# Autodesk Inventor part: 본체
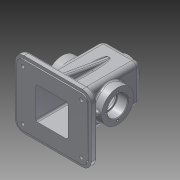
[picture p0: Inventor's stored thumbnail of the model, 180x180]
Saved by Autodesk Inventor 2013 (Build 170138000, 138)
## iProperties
Created: 2016-01
Part Number: 본체
Material: 알루미늄 6061
Document SubType Name: Modeling
Designer: User
Density: 2.71 g/cm^3
Mass: 889.915 g
Surface Area: 961.713 cm^2
Volume: 328.382 cm^3
Author: User
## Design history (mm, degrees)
sketch "스케치1"
  geometry: L1 (-32.5, 55)-(32.5, 55); L2 (32.5, 55)-(32.5, -55); L3 (32.5, -55)-(-32.5, -55); L4 (-32.5, -55)-(-32.5, 55); 1 further point
  constraints: 8 end point, 2 parallel, 1 horizontal, 1 perpendicular
  dimensions: "d0" = 65 distance of L1.start L1.end; "d2" = 110 distance of L3.end L1.start; "d3" = 32.5 distance from line of point (0, 0) L4; "d4" = 55 distance from line of point (0, 0) L1
extrude "돌출1" new body sketch "스케치1" stored distance "d5" = 65; taper "d6" = 0 deg
sketch "스케치2"
  geometry: L1 (65, 0)-(65, -65) reference; L2 (0, 0)-(65, 0) reference; L3 (0, 0)-(0, -65) reference; L4 (65, -65)-(0, -65) reference; L5 (5, -5)-(60, -5); L6 (60, -5)-(60, -60); L7 (60, -60)-(5, -60); L8 (5, -60)-(5, -5); 1 further point
  constraints: 8 end point, 2 parallel, 1 horizontal, 1 perpendicular
  dimensions: "d7" = 5 distance between parallel lines of L8 L3; "d8" = 5 distance between parallel lines of L2 L5; "d9" = 5 distance between parallel lines of L1 L6; "d10" = 5 distance between parallel lines of L4 L7
extrude "돌출2" cut sketch "스케치2" distance "d11" = 105; taper "d12" = 0 deg
node "작업 평면1"
sketch "스케치3"
  geometry: C1 r 20 at (32.5, 32.5); 1 further point
  constraints: 1 centre point, 1 coincident
  dimensions: "d14" = 40 diameter of C1
extrude "돌출3" join sketch "스케치3" stored distance "d15" = 105; taper "d16" = 0 deg
hole "구멍1" diameter "d19" = 21; stored, may be unused: countersink angle "d23" = 90 deg, drill point angle "d25" = 118 deg; dims "d17" = 10, "d18" = 10, "d20" = 6, "d21" = 4, "d22" = 2, "d24" = 8
node "작업 평면2"
sketch "스케치5"
  geometry: C1 r 27.5 at (32.5, 55); 1 further point
  constraints: 1 centre point, 1 coincident
  dimensions: "d28" = 55 diameter of C1
extrude "돌출4" join sketch "스케치5" stored distance "d29" = 105; taper "d30" = 0 deg
hole "구멍2" diameter "d33" = 35; stored, may be unused: countersink angle "d37" = 90 deg, drill point angle "d39" = 0 deg; dims "d31" = 10, "d32" = 10, "d34" = 6, "d35" = 4, "d36" = 2, "d38" = 17
hole "구멍3" diameter "d42" = 30; stored, may be unused: countersink angle "d46" = 90 deg, drill point angle "d48" = 0 deg; dims "d40" = 10, "d41" = 10, "d43" = 6, "d44" = 4, "d45" = 2, "d47" = 17
node "작업 평면3"
sketch "스케치6"
  geometry: L1 (-65, 57.5)-(65, 57.5); L2 (65, 57.5)-(65, -57.5); L3 (65, -57.5)-(-65, -57.5); L4 (-65, -57.5)-(-65, 57.5); 1 further point
  constraints: 8 end point, 2 parallel, 1 horizontal, 1 perpendicular
  dimensions: "d50" = 130 distance of L1.start L1.end; "d52" = 115 distance of L1.end L2.end; "d53" = 65 distance from line of point (0, 0) L4; "d54" = 57.5 distance from line of point (0, 0) L1
extrude "돌출5" join sketch "스케치6" distance "d55" = 10; taper "d56" = 0 deg
node "작업 평면4"
sketch "스케치8"
  geometry: L1 (-60, 52.5)-(60, 52.5); L2 (60, 52.5)-(60, -52.5); L3 (60, -52.5)-(-60, -52.5); L4 (-60, -52.5)-(-60, 52.5); L5 (65, -57.5)-(65, 57.5) reference; L6 (65, 57.5)-(-65, 57.5) reference; L7 (-27.5, 27.5)-(27.5, 27.5); L8 (27.5, 27.5)-(27.5, -27.5); L9 (27.5, -27.5)-(-27.5, -27.5); L10 (-27.5, -27.5)-(-27.5, 27.5); 1 further point
  constraints: 16 end point, 4 parallel, 2 horizontal, 2 perpendicular
  dimensions: "d61" = 120 distance of L1.start L1.end; "d63" = 105 distance of L1.end L2.end; "d64" = 5 distance between parallel lines of L5 L2; "d65" = 5 distance between parallel lines of L6 L1; "d66" = 55 distance of L7.start L7.end; "d67" = 55 distance of L7.end L8.end; "d68" = 27.5 distance from line of point (0, 0) L7; "d70" = 27.5 distance from line of point (0, 0) L10
extrude "돌출6" join sketch "스케치8" stored distance "d71" = 10; taper "d72" = 0 deg
extrude "돌출7" cut sketch "스케치8" distance "d73" = 89.75; taper "d74" = 0 deg
sketch "스케치9"
  geometry: L1 (-53, 57.5)-(-63, 57.5) reference; L2 (-53, 57.5)-(-53, -57.5) reference; L3 (55, 32.5)-(-53, 32.5) reference; L4 (-53, 47.5)-(32.069, 32.5); 1 further point
  constraints: 2 end point, 2 point on line
  dimensions: "d79" = 10 distance from line of L1 L4.start; "d80" = 10 deg angle of L1 L4
feature "리브1" sketch "스케치9" dims "d81" = 1, "d82" = 10, "d83" = 0, "d84" = 0, "d85" = 1, "d86" = 1
sketch "스케치11"
  geometry: L1 (-27.5, -65)-(-27.5, 50) reference; L2 (-65, -53)-(65, -53) reference; L3 (-42.5, -53)-(-42.5, -22.279); 1 further point
  constraints: 2 end point, 1 perpendicular, 1 point on line
  dimensions: "d87" = 15 distance from line of L1 L3.start
feature "리브2" sketch "스케치11" dims "d88" = 1, "d89" = 6, "d90" = 0, "d91" = 0, "d92" = 1, "d93" = 1
sketch "스케치12"
  geometry: L1 (-65, 57.5)-(65, 57.5) reference; C1 r 7.5 at (-50, 42.5); C2 r 7.5 at (50, 42.5); C3 r 7.5 at (50, -42.5); C4 r 7.5 at (-50, -42.5); 1 further point
  constraints: 4 centre point, 1 horizontal alignment
  dimensions: "d94" = 15 diameter of C1; "d95" = 15 diameter of C2; "d96" = 15 diameter of C3; "d97" = 15 diameter of C4; "d99" = 15 distance from line of C1.centre L1; "d100" = 100 distance of C2.centre C1.centre; "d102" = 85 distance of C4.centre C1.centre; "d103" = 100 distance of C3.centre C4.centre; "d105" = 42.5 vertical distance of point (0, 0) C2.centre; "d106" = 50 horizontal distance of C3.centre point (0, 0); "d187" = 50 horizontal distance of point (0, 0) C1.centre
extrude "돌출8" join sketch "스케치12" distance "d107" = 3; taper "d108" = 0 deg
hole "구멍4" diameter "d111" = 6; stored, may be unused: countersink angle "d115" = 90 deg, drill point angle "d117" = 0 deg; dims "d109" = 10, "d110" = 10, "d112" = 6, "d113" = 4, "d114" = 2, "d116" = 17
hole "구멍5" diameter "d120" = 6; stored, may be unused: countersink angle "d124" = 90 deg, drill point angle "d126" = 0 deg; dims "d118" = 10, "d119" = 10, "d121" = 6, "d122" = 4, "d123" = 2, "d125" = 17
hole "구멍6" diameter "d129" = 6; stored, may be unused: countersink angle "d133" = 90 deg, drill point angle "d135" = 0 deg; dims "d127" = 10, "d128" = 10, "d130" = 6, "d131" = 4, "d132" = 2, "d134" = 17
hole "구멍7" diameter "d138" = 6; stored, may be unused: countersink angle "d142" = 90 deg, drill point angle "d144" = 0 deg; dims "d136" = 10, "d137" = 10, "d139" = 6, "d140" = 4, "d141" = 2, "d143" = 17
node "작업 평면7"
feature "면 기울기1" dims angle "d145" = 5 deg
sketch "스케치13"
  geometry: L1 (-78.073, 0)-(132.155, 0); C1 r 10.5 at (0, 0) reference; C2 r 20 at (0, 0) reference; C3 r 1.5 at (0, 14.5); C4 r 1.5 at (-14.5, 0); C5 r 1.5 at (0, -14.5); C6 r 1.5 at (14.5, 0)
  constraints: 4 centre point, 2 end point, 1 horizontal, 1 point on line, 1 vertical alignment, 9 other
  dimensions: "d146" = 3 diameter of C3; "d147" = 29 diameter of C3.centre L1; "d150" = 360 deg dimension on C2.centre C3.centre (derived)
hole "구멍8" sketch "스케치13" at (-14.5, 0), (0, 14.5), (14.5, 0), (0, -14.5) diameter "d152" = 2.459; stored, may be unused: countersink angle "d156" = 90 deg, drill point angle "d158" = 0 deg; dims "d153" = 7, "d154" = 4, "d155" = 2, "d157" = 9
sketch "스케치14"
  geometry: L1 (-64.422, 0)-(123.164, 0); C1 r 27.5 at (0, 0) reference; C2 r 2 at (0, 21); C3 r 2 at (-21, 0); C4 r 2 at (0, -21); C5 r 2 at (21, 0)
  constraints: 4 centre point, 2 end point, 1 horizontal, 1 point on line, 1 vertical alignment, 9 other
  dimensions: "d159" = 4 diameter of C2; "d160" = 42 diameter of C2.centre L1; "d163" = 360 deg dimension on C1.centre C2.centre (derived)
hole "구멍9" sketch "스케치14" at (0, 21), (21, 0), (0, -21), (-21, 0) diameter "d165" = 3.242; stored, may be unused: countersink angle "d169" = 90 deg, drill point angle "d171" = 0 deg; dims "d166" = 8, "d167" = 4, "d168" = 2, "d170" = 10
fillet "모깎기1" dims "d172" = 15
fillet "모깎기2" dims "d173" = 3
fillet "모깎기3" dims "d174" = 8
fillet "모깎기5" dims "d176" = 8
fillet "모깎기6" dims "d177" = 3
fillet "모깎기7" dims "d178" = 3
chamfer "모따기1" distance "d179" = 1; stored, may be unused: second distance "d180" = 2, angle "d181" = 45 deg
fillet "모깎기8" dims "d185" = 3
sketch "스케치15"
  geometry: L1 (4.5, 18)-(44.5, 18) reference; L2 (-8, 0)-(-8, -97) reference; 1 further point
  constraints: 1 other
  dimensions: "d188" = 26 distance from line of point (24.5, -8) L1; "d189" = 32.5 distance from line of L2 point (24.5, -8)
feature "엠보싱1" sketch "스케치15" dims "d190" = 0.5, "d191" = 0
fillet "모깎기10" dims "d192" = 3
fillet "모깎기11" dims "d196" = 0.3
fillet "모깎기13" dims "d198" = 10
node "솔리드1"
mirror "대칭1"
mirror "대칭2"
mirror "대칭3"
mirror "대칭4"
other parameters: "d27" = 15, "d49" = -53, "d60" = 2
